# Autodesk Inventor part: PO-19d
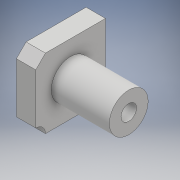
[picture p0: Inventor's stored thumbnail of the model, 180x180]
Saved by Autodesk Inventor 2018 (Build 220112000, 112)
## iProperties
Created: 2020-01
Part Number: PO-19d
Material: Générique
Document SubType Name: Modeling
Designer: TJ
Density: 1 g/cm^3
Appearance: Par défaut
Author: TJ
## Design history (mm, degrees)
sketch "Esquisse1"
  geometry: L1 (18, 18)-(-18, 18); L2 (-18, 18)-(-18, -18); L3 (-18, -18)-(18, -18); L4 (18, -18)-(18, 18); 1 further point
  constraints: 8 end point, 2 parallel, 1 horizontal, 1 perpendicular
  dimensions: "d0" = 36 distance of L3.end L1.start; "d1" = 36 distance of L1.start L1.end (= d0); "d2" = 18 distance from line of L4 point (0, 0) (= 0.5 x d0); "d3" = 18 distance from line of L1 point (0, 0) (= 0.5 x d0)
extrude "Extrusion1" new body sketch "Esquisse1" distance "d4" = 10; taper "d5" = 0 deg
sketch "Esquisse3"
  geometry: L1 (-10, 10)-(10, 10); L2 (10, 10)-(10, -10); L3 (10, -10)-(-10, -10); L4 (-10, -10)-(-10, 10); L5 (-10, 10)-(10, -10); L6 (10, 10)-(-10, -10); 1 further point
  constraints: 12 end point, 2 midpoint, 2 parallel, 1 horizontal, 1 perpendicular
  dimensions: "d10" = 20 distance of L1.start L1.end; "d11" = 20 distance of L3.end L1.start (= d10)
extrude "Extrusion3" join sketch "Esquisse3" distance "d12" = 30; taper "d13" = 0 deg
sketch "Esquisse5"
  geometry: L1 (-4, -4)-(4, -4); L2 (4, -4)-(4, 4); L3 (4, 4)-(-4, 4); L4 (-4, 4)-(-4, -4); L5 (-4, -4)-(4, 4); L6 (4, -4)-(-4, 4); 1 further point
  constraints: 12 end point, 2 midpoint, 2 parallel, 1 horizontal, 1 perpendicular
  dimensions: "d17" = 8 distance of L3.end L1.start; "d18" = 8 distance of L2.end L3.end
extrude "Extrusion5" cut sketch "Esquisse5" extent not by distance; stored distance "d19" = 10; taper "d20" = 0 deg
fillet "Congé3" dims "d25" = 4
sketch "Esquisse6"
  geometry: L1 (-18, -18)-(18, -18) reference; C1 r 5 at (18, -18); 1 further point
  constraints: 1 centre point
  dimensions: "d26" = 10 diameter of C1
extrude "Extrusion6" cut sketch "Esquisse6" extent not by distance; stored distance "d27" = 10; taper "d28" = 0 deg
chamfer "Chanfrein2" distance "d29" = 5; stored, may be unused: second distance "d30" = 2, angle "d31" = 45 deg
fillet "Congé4" dims "d32" = 10
node "Solide1"
other parameters: "sa_0" = 4
